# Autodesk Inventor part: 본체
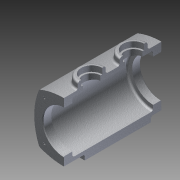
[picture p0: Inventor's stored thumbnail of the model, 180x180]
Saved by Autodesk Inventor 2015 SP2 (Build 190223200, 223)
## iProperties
Created: 2013-02
Part Number: 본체
Document SubType Name: Modeling
Designer: 한국산업디자인학원[gmhk.co.kr]
Density: 1 g/cm^3
Material: 일반
Appearance: _시험_알루미늄 표면거칠기
Author: 한국산업디자인학원[gmhk.co.kr]
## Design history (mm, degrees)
sketch "스케치1"
  geometry: L1 (-65, 55)-(65, 55); L2 (65, 55)-(65, -40); L3 (65, -40)-(-65, -40); L4 (-65, -40)-(-65, 55); 2 further points
  constraints: 8 end point, 2 parallel, 1 horizontal, 1 midpoint, 1 perpendicular, 1 vertical alignment
  dimensions: "d0" = 130 distance of L2.end L3.end; "d1" = 95 distance of L1.end L2.end; "d47" = 40 distance from line of L3 point (0, 0)
extrude "돌출1" new body sketch "스케치1" distance "d2" = 12; taper "d3" = 0 deg
sketch "스케치2"
  geometry: L1 (-35.355, 85.355)-(35.355, 85.355); L2 (35.355, 85.355)-(35.355, 14.645); L3 (35.355, 14.645)-(-35.355, 14.645); L4 (-35.355, 14.645)-(-35.355, 85.355); L5 (35.355, 85.355)-(-35.355, 14.645); L6 (65, 0)-(-65, 0) reference; A1 r 91.05 centre (0, 1.45) between (35.355, 85.355) and (-35.355, 85.355); A2 r 91.05 centre (-48.55, 50) between (35.355, 14.645) and (35.355, 85.355); A3 r 91.05 centre (0, 98.55) between (-35.355, 14.645) and (35.355, 14.645); A4 r 91.05 centre (48.55, 50) between (-35.355, 85.355) and (-35.355, 14.645); 3 further points
  constraints: 10 end point, 8 point on circle, 4 centre point, 3 equal radius, 2 midpoint, 2 parallel, 2 perpendicular, 1 horizontal, 1 vertical alignment
  dimensions: "d4" = 50 distance from line of point (0, 50) L6; "d5" = 50 distance of L1.start point (0, 50); "d6" = 85 dimension on A2 A4
extrude "돌출2" join sketch "스케치2" stored distance "d7" = 140; taper "d8" = 0 deg
sketch "스케치3"
  geometry: L1 (28.27, 12)-(65, 12) reference; L2 (-65, 12)-(-28.27, 12) reference; A1 r 91.05 centre (0, 98.55) between (-35.355, 14.645) and (35.355, 14.645) reference; A2 r 91.05 centre (48.55, 50) between (-35.355, 85.355) and (-35.355, 14.645) reference; A3 r 91.05 centre (-48.55, 50) between (35.355, 14.645) and (35.355, 85.355) reference; A4 r 5 centre (-41.653, 17) between (-41.653, 12) and (-36.957, 18.718); A5 r 5 centre (41.653, 17) between (36.957, 18.718) and (41.653, 12); 1 further point
  constraints: 6 point on circle, 4 tangent, 2 centre point, 2 point on line, 1 equal radius
  dimensions: "d9" = 5 radius of A5
extrude "돌출3" join sketch "스케치3" stored distance "d10" = 120; taper "d11" = 0 deg
fillet "모깎기1" dims "d12" = 3
fillet "모깎기2" dims "d13" = 10
fillet "모깎기3" dims "d14" = 3
sketch "스케치4"
  geometry: L1 (-70, 84.185)-(-70, 85.839) reference; L2 (-70, 15.815)-(-70, 84.185) reference; L3 (-70, 14.161)-(-70, 15.815) reference; L4 (-70, 14.161)-(-70, 14.161) reference; L5 (-70, 15.815)-(-70, 14.161) reference; L6 (-70, 84.185)-(-70, 15.815) reference; L7 (-70, 85.839)-(-70, 84.185) reference; L8 (-70, 85.839)-(-70, 85.839) reference; L9 (70, 15.815)-(70, 14.161) reference; L10 (70, 84.185)-(70, 15.815) reference; L11 (70, 85.839)-(70, 84.185) reference; L12 (70, 85.839)-(70, 85.839) reference; L13 (70, 84.185)-(70, 85.839) reference; L14 (70, 15.815)-(70, 84.185) reference; L15 (70, 14.161)-(70, 15.815) reference; L16 (70, 14.161)-(70, 14.161) reference; L17 (-70, 50)-(70, 50); L18 (-70, 80)-(-58, 80); L19 (-58, 80)-(-58, 87.5); L20 (-58, 87.5)-(58, 87.5); L21 (58, 87.5)-(58, 80); L22 (58, 80)-(70, 80); 1 further point
  constraints: 12 end point, 2 collinear, 2 midpoint, 2 parallel, 2 perpendicular, 2 point on line
  dimensions: "d15" = 60 diameter of L18 L17; "d16" = 75 diameter of L20 L17; "d17" = 12 distance of L18.start L18.end; "d18" = 12 distance of L21.end L22.end
revolve "회전1" sketch "스케치4" stored, may be unused: angle "d19" = 90 deg
fillet "모깎기4" dims "d20" = 3
node "작업 평면2"
  node "작업 평면1"
sketch "스케치5"
  geometry: C1 r 20 at (0, 30); C2 r 20 at (0, -30); 1 further point
  constraints: 2 centre point, 2 vertical alignment
  dimensions: "d22" = 40 diameter of C1; "d23" = 40 diameter of C2; "d24" = 60 distance of C2.centre C1.centre; "d25" = 30 distance of point (0, 0) C1.centre (= 0.5 x d24)
extrude "돌출4" join sketch "스케치5" stored distance "d26" = 120; taper "d27" = 0 deg
fillet "모깎기5" dims "d28" = 3
hole "구멍1" diameter "d31" = 25; stored, may be unused: countersink angle "d35" = 90 deg, drill point angle "d37" = 118 deg; dims "d29" = 10, "d30" = 10, "d32" = 6, "d33" = 30, "d34" = 8, "d36" = 8
hole "구멍2" diameter "d40" = 25; stored, may be unused: countersink angle "d44" = 90 deg, drill point angle "d46" = 118 deg; dims "d38" = 10, "d39" = 10, "d41" = 6, "d42" = 30, "d43" = 8, "d45" = 8
sketch "스케치6"
  geometry: L1 (65, -30)-(65, 45) reference; 4 further points
  constraints: 1 midpoint, 1 vertical alignment
  dimensions: "d48" = 13 distance from line of point (52, 42.5) L1; "d49" = 70 distance of point (52, -27.5) point (52, 42.5); "d50" = 35 vertical distance of point (65, 7.5) point (52, 42.5) (= 0.5 x d49)
hole "구멍3" sketch "스케치6" at (52, -27.5), (52, 42.5) diameter "d51" = 11; stored, may be unused: countersink angle "d55" = 90 deg, drill point angle "d57" = 118 deg; dims "d52" = 6, "d53" = 30, "d54" = 8, "d56" = 8
sketch "스케치8"
  geometry: L1 (65, -30)-(65, 45) reference; 3 further points
  constraints: 1 horizontal alignment, 1 midpoint, 1 other
  dimensions: "d60" = 8 distance from line of point (57, 7.5) L1
feature "엠보싱2" sketch "스케치8" dims "d0" = 130, "d1" = 95, "d47" = 40, "d61" = 1, "d62" = 0
chamfer "모따기1" distance "d63" = 1; stored, may be unused: second distance "d64" = 2, angle "d65" = 45 deg
sketch "스케치9"
  geometry: L1 (0, 81)-(0, 50); L2 (0, 50)-(28.284, 78.284); 1 further point
  constraints: 4 end point, 1 vertical, 1 vertical alignment, 1 other
  dimensions: "d66" = 45 deg angle of L2 L1; "d67" = 40 distance of L2.end L1.end
hole "구멍4" sketch "스케치9" at (28.284, 78.284) diameter "d68" = 3.242; stored, may be unused: countersink angle "d72" = 90 deg, drill point angle "d74" = 118 deg; dims "d69" = 8, "d70" = 30, "d71" = 8, "d73" = 10
sketch "스케치10"
  geometry: L1 (0, -36.013)-(104.944, -36.013); L2 (104.944, -36.013)-(104.944, 121.651); L3 (104.944, 121.651)-(0, 121.651); L4 (0, 121.651)-(0, -36.013); 1 further point
  constraints: 8 end point, 2 parallel, 1 horizontal, 1 perpendicular
extrude "돌출5" cut sketch "스케치10" distance "d78" = 123123; taper "d79" = 0 deg
node "솔리드1"
mirror "대칭1"
pattern_circular "원형 패턴1" dims angle "d76" = 360 deg
mirror "대칭2"
node "투영된 루프1"
node "투영된 루프2"
